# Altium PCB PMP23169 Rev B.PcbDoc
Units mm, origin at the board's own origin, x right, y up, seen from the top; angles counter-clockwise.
Board outline 125.73 x 87.63 mm, 2 copper layers (Top Layer, Bottom Layer), stack 1.575 mm thick; 44 components, 13 nets, 91 pads, 0 vias.
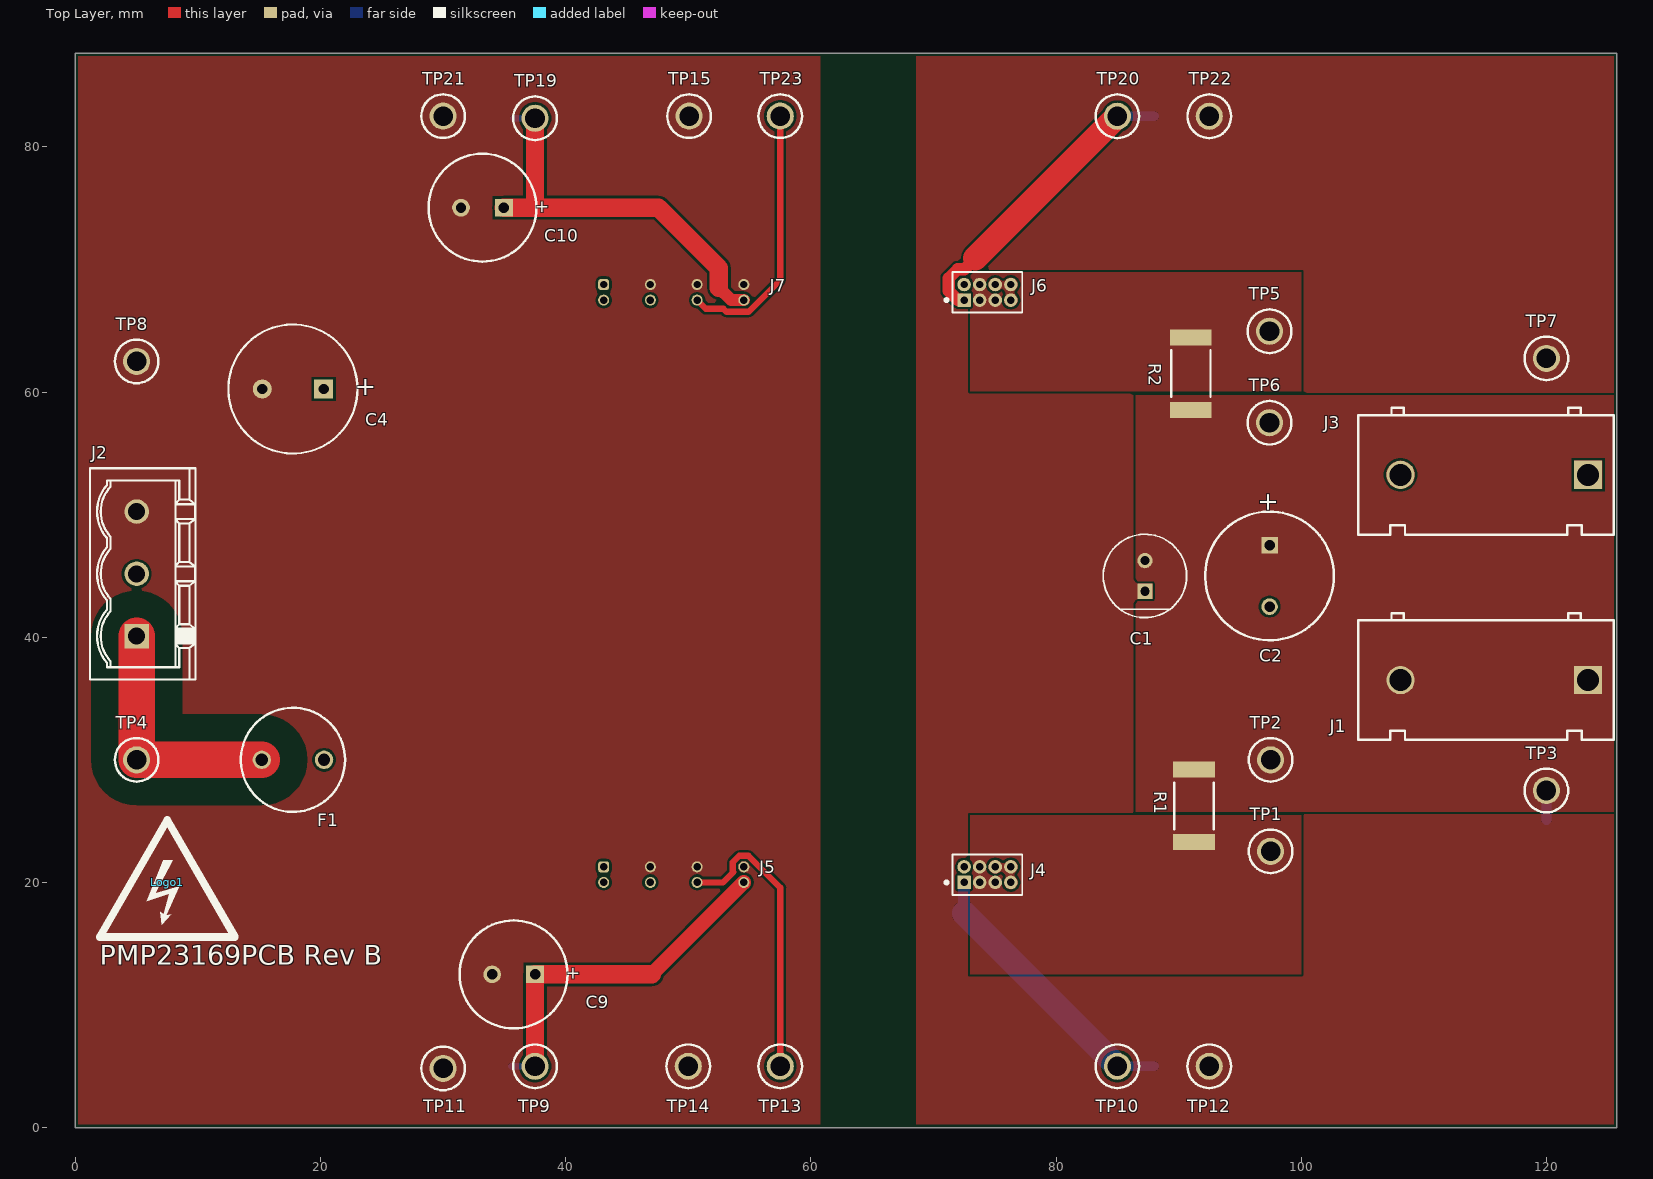
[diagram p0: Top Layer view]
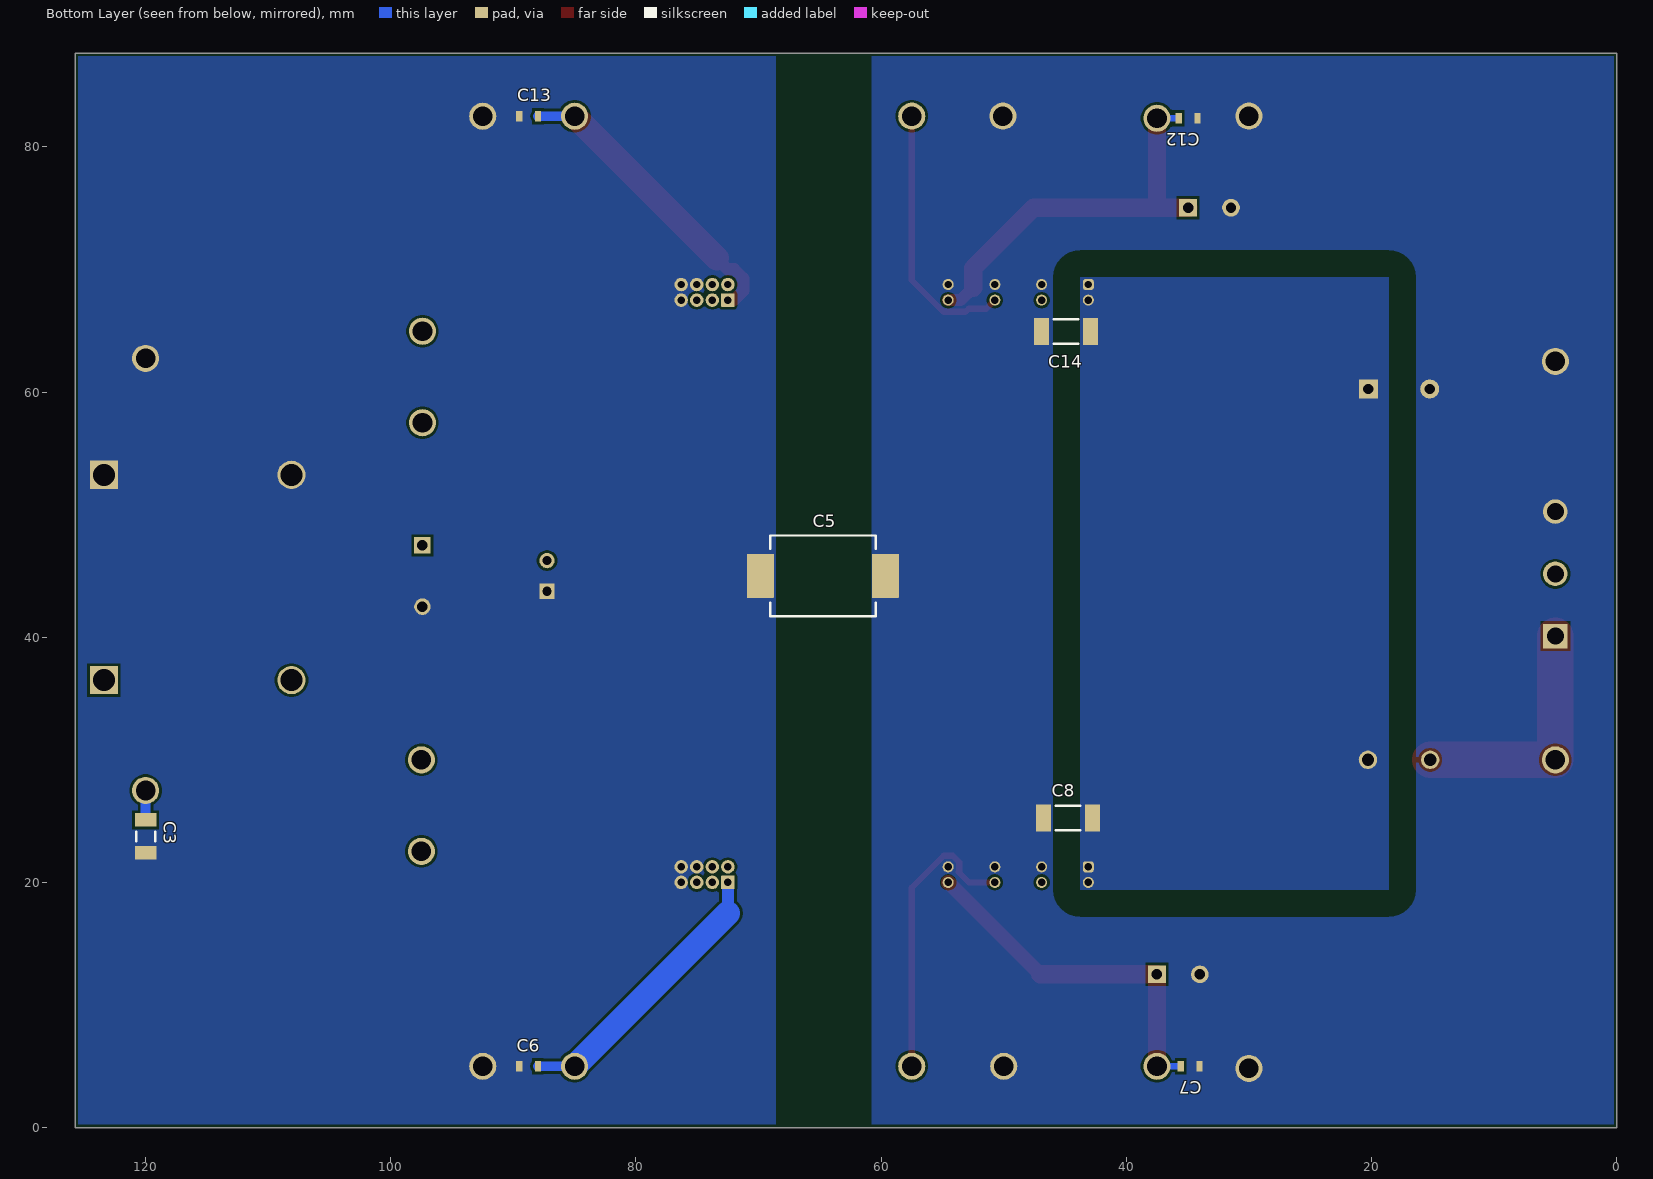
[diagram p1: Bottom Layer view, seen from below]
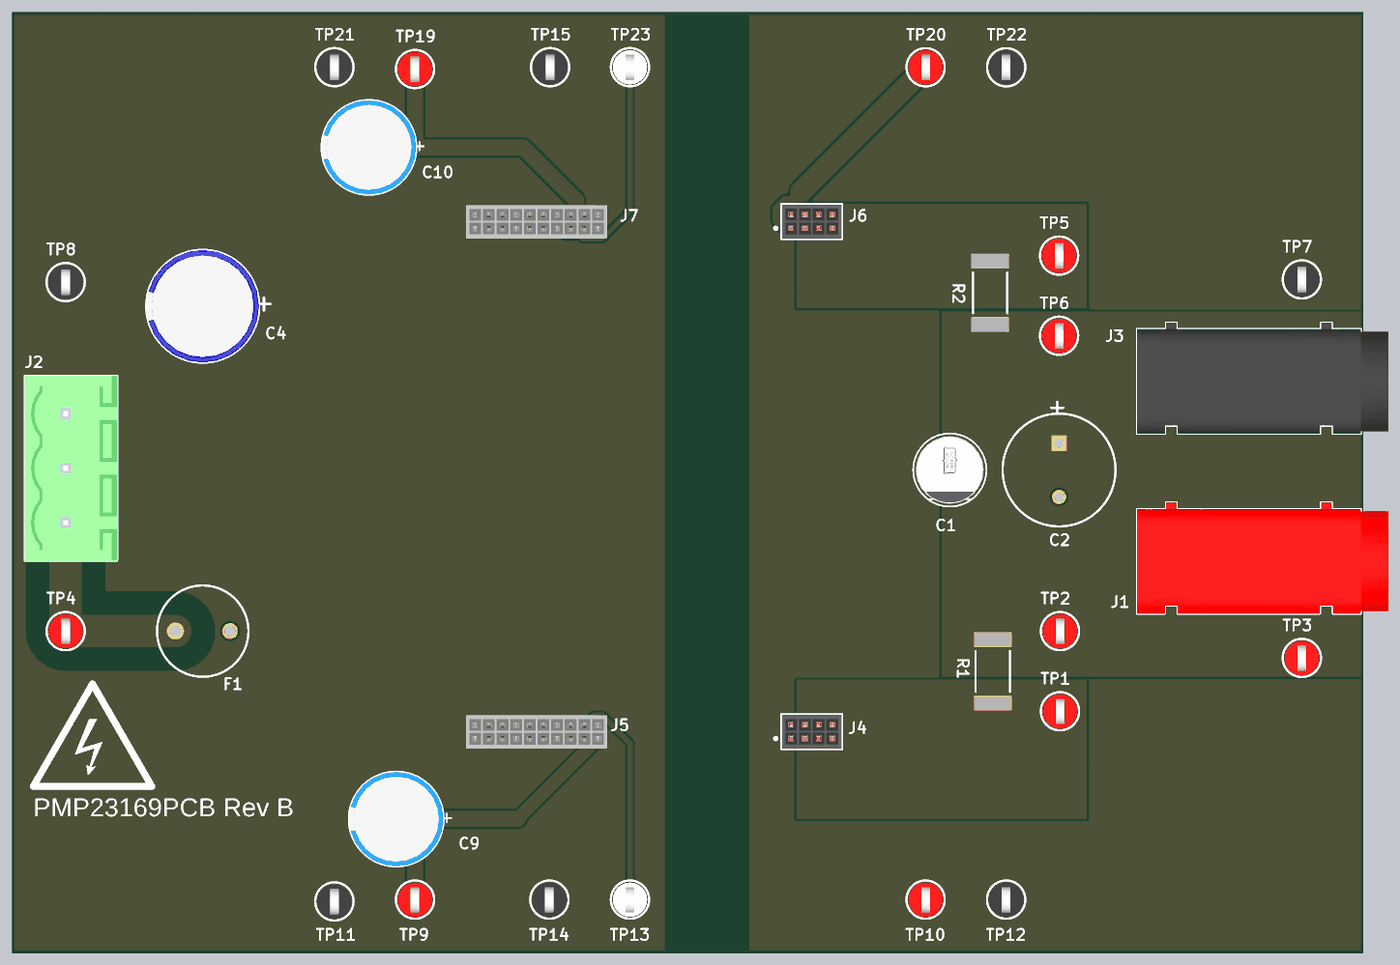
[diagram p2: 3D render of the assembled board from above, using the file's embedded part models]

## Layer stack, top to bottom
Top Solder: solder mask 0.0102, Solder Resist, Dk 3.5
Top Layer: signal copper 0.0356
Dielectric1: core 1.5037, FR-4 High Tg, Dk 4.8
Bottom Layer: signal copper 0.0356
Bottom Solder: solder mask 0.0102, Solder Resist, Dk 3.5

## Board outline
0,0 125.73,0 125.73,87.63 0,87.63

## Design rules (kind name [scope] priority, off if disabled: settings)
AcuteAngle [All] p1: minimum=5.00000000000000E+0000 checktracksonly=FALSE
AssemblyTestPointUsage [All] p1: valid=2
BoardOutlineClearance BoardOutlineClearance_Pri [InNet('P')] p1: gap=0.4 ignorepadtopadclearanceinfootprint=FALSE
BoardOutlineClearance BoardOutlineClearance_MountingHoles [OnCopper and InComponentClass('Mounting Holes')] p2: gap=0.635 ignorepadtopadclearanceinfootprint=FALSE
BoardOutlineClearance BoardOutlineClearance_Poly [OnCopper and InPoly] p3: gap=0.25 ignorepadtopadclearanceinfootprint=FALSE
BoardOutlineClearance [OnCopper and Not InComponentClass('Logo') and not InComponentClass('FiducialMark') and not InRegion(1000,500,4000,800)] p4: gap=0.25 ignorepadtopadclearanceinfootprint=FALSE
Clearance "Pri To Sec Inner Layers" [InNet('S') vs InNet('A')  Or InNet('B')] p1: gap=0.5 ignorepadtopadclearanceinfootprint=TRUE
Clearance "400V Clearance" [(InNetClass('400V') AND (OnTopLayer Or OnBottomLayer)) vs (InNetClass('Primary LV'))] p2: gap=2.2 ignorepadtopadclearanceinfootprint=TRUE
Clearance "Float Bias Clearance" [(InNetClass('BIAS_FLOAT') AND (OnTopLayer Or OnBottomLayer)) vs (InNetClass('Primary LV'))] p3: gap=2.2 ignorepadtopadclearanceinfootprint=TRUE
Clearance Clearance_Keepouts [((IsTrack Or IsArc) And Not InPoly) And IsFree and IsKeepOut vs ((IsTrack Or IsArc) And Not InPoly) And IsFree and IsKeepOut] p4: gap=0 ignorepadtopadclearanceinfootprint=TRUE
Clearance Clearance_Poly [InPolygon] p5: gap=0.203 ignorepadtopadclearanceinfootprint=TRUE except(0: Arc-Hole Track-Hole SMDPad-Hole THPad-Hole Via-Hole Fill-Hole Poly-Hole Region-Hole Text-Hole)
Clearance [All] p6: gap=0.2 ignorepadtopadclearanceinfootprint=TRUE except(0: Arc-Hole Track-Hole SMDPad-Hole THPad-Hole Via-Hole Fill-Hole Poly-Hole Region-Hole Text-Hole)
ComponentClearance ComponentClearance_MountingHoles_FiducialMarks [InComponentClass('Mounting Holes') vs InComponentClass('FiducialMark')] p1: gap=1.27 collisioncheckmode=3 verticalgap=0.254 showdistances=FALSE
ComponentClearance ComponentClearance_Shunt [InComponentClass('Header') vs InComponentClass('Shunt')] p2: gap=0 collisioncheckmode=3 verticalgap=0 showdistances=FALSE
ComponentClearance ComponentClearance_Logo [InComponentClass('Logo')] p3: gap=1.27 collisioncheckmode=3 verticalgap=0.254 showdistances=FALSE
ComponentClearance ComponentClearance_ScrewToNut [(HasFootprint('NY PMS 440 0025 PH')) vs (HasFootprint('Keystone_1902C'))] p4: gap=0.127 collisioncheckmode=3 verticalgap=0.254 showdistances=FALSE
ComponentClearance ComponentClearance_MountingHoles [InComponentClass('Mounting Holes')] p5: gap=6.35 collisioncheckmode=3 verticalgap=2540 showdistances=FALSE
ComponentClearance ComponentClearance_SmallPassives [HasFootprint('0201*') or HasFootprint('0402*') or HasFootprint('0508') or HasFootprint('0603*') or HasFootprint('0612') or HasFootprint('0805*') or HasFootprint('0815*') or HasFootprint('0830*') or HasFootprint('1206*') or HasFootprint('1210*') or HasFootprint('1808*') or HasFootprint('1812*') or HasFootprint('1825*') or HasFootprint('2010*') or HasFootprint('2220*') or HasFootprint('2225*') or HasFootprint('2512*') or HasFootprint('2728*') or HasFootprint('3518*') vs HasFootprint('0201*') or HasFootprint('0402*') or HasFootprint('0508') or HasFootprint('0603*') or HasFootprint('0612') or HasFootprint('0805*') or HasFootprint('0815*') or HasFootprint('0830*') or HasFootprint('1206*') or HasFootprint('1210*') or HasFootprint('1808*') or HasFootprint('1812*') or HasFootprint('1825*') or HasFootprint('2010*') or HasFootprint('2220*') or HasFootprint('2225*') or HasFootprint('2512*') or HasFootprint('2728*') or HasFootprint('3518*')] p6: gap=0.38 collisioncheckmode=3 verticalgap=0.254 showdistances=FALSE
ComponentClearance ComponentClearance_THtoSMT [IsThruComponent vs IsSMTComponent] p7: gap=0.381 collisioncheckmode=3 verticalgap=0.762 showdistances=FALSE
ComponentClearance ComponentClearance_THtoTH [IsThruComponent vs IsThruComponent] p8: gap=0.381 collisioncheckmode=3 verticalgap=0.762 showdistances=FALSE
ComponentClearance [All] p9: gap=0.381 collisioncheckmode=3 verticalgap=0.254 showdistances=FALSE
DiffPairsRouting [All] p1: maxlimit=2.54 minlimit=0.254 mostfreqgap=0.254 toplayer_minwidth=0.381 toplayer_maxwidth=0.381 toplayer_prefwidth=0.381 bottomlayer_minwidth=0.381 bottomlayer_maxwidth=0.381 bottomlayer_prefwidth=0.381 maxuncoupledlength=25.4
FabricationTestPointUsage TestPointUsage [All] p1: valid=2 allowmultiple=FALSE
FabricationTestpoint Testpoint [All] p1: side=3 testpointundercomponent=TRUE minsize=1.016 maxsize=2.54 preferedsize=1.524 minholesize=0 maxholesize=1.016 preferedholesize=0.813 testpointgrid=0.025 allowsidetop=TRUE allowsidebottom=TRUE usegrid=TRUE gridtolerance=0
FanoutControl Fanout_LCC [IsLCC] p1: bgadir=Out bgaviamode=Centered fanoutstyle=Auto fanoutdirection=Alternating viagrid=0.025 // Fanout_LCC (Default Rule)
FanoutControl Fanout_BGA [IsBGA] p2: bgadir=Out bgaviamode=Centered fanoutstyle=Auto fanoutdirection=Alternating viagrid=0.025 // Fanout_BGA (Default Rule)
FanoutControl Fanout_Default [All] p4: bgadir=Out bgaviamode=Centered fanoutstyle=Auto fanoutdirection=Alternating viagrid=0.025 // Fanout_Default (Default Rule)
FanoutControl Fanout_Small [(CompPinCount < 5)] p5: bgadir=Out bgaviamode=Centered fanoutstyle=Auto fanoutdirection=OutThenIn viagrid=0.025 // Fanout_Small (Default Rule)
HoleSize [All] p1: absolutevalues=TRUE maxlimit=6.375 minlimit=0.2 maxpercent=80.000 minpercent=20.000
MinimumAnnularRing MinimumAnnularRing_ThermalPadVias [IsVia and InAnyComponent] p1: minimumring=0.15
MinimumAnnularRing [All] p2: minimumring=0.15
MinimumSolderMaskSliver MinimumSolderMaskSliver_Logo [InComponentClass('Logo') vs InComponentClass('Logo')] p1 off: minsoldermaskwidth=0.018
MinimumSolderMaskSliver [All] p2 off: minsoldermaskwidth=0.025
PlaneConnect [All] p1: planeconnectstyle=Direct reliefexpansion=0.254 reliefentries=4 reliefconductorwidth=0.254 reliefairgap=0.254
PolygonConnect [All] p1: connectstyle=Direct reliefconductorwidth=0.381 reliefentries=4 polygonreliefangle="90 Angle" airgapwidth=0.254
RoutingVias ThermalPadVias [IsVia and InAnyComponent] p1: holewidth=0.2 width=0.5 viastyle="Through Hole" minholewidth=0.2 minwidth=0.5 maxholewidth=0.33 maxwidth=0.6
RoutingVias [All] p2: holewidth=0.406 width=0.864 viastyle="Through Hole" minholewidth=0.2 minwidth=0.65 maxholewidth=1.016 maxwidth=1.651
SilkToBoardRegionClearance [Not ((IsComment or IsDesignator) And (Hide <> 'False')) and not InRegion(1000,500,4000,800)] p1:
SilkToSilkClearance SilkToSilkClearance_Pb-FreeLogo [(HasFootprint('Pb-Free_Overlay_Medium') OR HasFootprint('Pb-Free_Overlay_Small')) vs (HasFootprint('Pb-Free_Overlay_Medium') OR HasFootprint('Pb-Free_Overlay_Small'))] p1: silktosilkclearance=0
SilkToSilkClearance [All] p2: silktosilkclearance=0.025
SilkToSolderMaskClearance SilkToComponentPadClearance [IsPad and InAnycomponent] p1: minsilkscreentomaskgap=0 clearancetoexposedcopper=TRUE
SilkToSolderMaskClearance "Silk to Solder Mask Opening" [All] p2: minsilkscreentomaskgap=0 clearancetoexposedcopper=FALSE
SolderMaskExpansion [All] p1: expansion=0.05 istentingtop=FALSE
Width [All] p1: maxlimit=4 minlimit=0.152 preferedwidth=0.254 checkconnectedcopper=TRUE
15 further rules are at their usual default settings.

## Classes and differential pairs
net class "Primary LV": PGND
net class 400V: NetF1_2 VIN

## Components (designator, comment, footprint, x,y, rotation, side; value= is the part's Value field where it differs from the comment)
C1 "APSG160ELL271MF08J" FP-APSG160ELL271MF08J_RADIAL-MFG 87.25,45 r90 top value=270µF
C2 "EKZE160ELL102MJ20S" Chemi-Con_1000x2000 97.415,45 r270 top value=1000uF
C3 "C3216X5R1V226M160AC" 1206_180L 120,23.75 r270 bottom value=22uF
C4 "EEUEE2W100U" EE_1000x2000 17.75,60.25 r180 top value=10uF
C5 "DK1E3EA152M86RAH01" DK1_86 64.75,45 r180 bottom value=1500pF
C6 "C1608X7R1E105K080AB" 0603S 88.762,5 r180 bottom value=1uF
C7 "C1608X7R1E105K080AB" 0603S 34.795,5 r0 bottom value=1uF
C8 "C1808W104KBRACTU" 1808_215_L 44.75,25.25 r0 bottom value=0.1uF
C9 "UBT1E101MPD1TD" BT_800x1150 35.75,12.5 r180 top value=100uF
C10 "UBT1E101MPD1TD" BT_800x1150 33.21,75.04 r180 top value=100uF
C12 "C1608X7R1E105K080AB" 0603S 34.96,82.336 r0 bottom value=1uF
C13 "C1608X7R1E105K080AB" 0603S 88.75,82.5 r180 bottom value=1uF
C14 "C1808W104KBRACTU" 1808_215_L 44.914,64.94 r0 bottom value=0.1uF
F1 "37205000001" FUSE_372 17.75,30 r180 top
J1 "571-0500" 571-0500 115.75,36.5 r180 top
J2 "1755749" CONN_1755749 5,45.17 r90 top
J3 "571-0100" 571-0100 115.75,53.25 r180 top
J4 "LPPB042CFFN-RC" FP-LPPB042CFFN-RC_HDR8-MFG 74.405,20.635 r0 top
J5 "LPPB102CFFN-RC" Sullins_LPPB102CFFN 48.815,20.635 r0 top
J6 "LPPB042CFFN-RC" FP-LPPB042CFFN-RC_HDR8-MFG 74.405,68.135 r0 top
J7 "LPPB102CFFN-RC" Sullins_LPPB102CFFN 48.815,68.135 r0 top
Logo1 "DANGER HIGH VOLTAGE" IEC_HighVoltage_Medium 7.5,20 r0 top (schematic designator LOGO1)
R1 "WSL2512R0100FEA" 2512 91.25,26.25 r90 top value=0.01
R2 "WSL2512R0100FEA" 2512 91,61.5 r270 top value=0.01
TP1 "5010" Keystone5010 97.5,22.536 r0 top
TP2 "5010" Keystone5010 97.5,30 r0 top
TP3 "5010" Keystone5010 120,27.5 r0 top
TP4 "5010" Keystone5010 5,30 r0 top
TP5 "5010" Keystone5010 97.415,64.963 r0 top
TP6 "5010" Keystone5010 97.415,57.5 r0 top
TP7 "5011" Keystone5011 120,62.75 r0 top
TP8 "5011" Keystone5011 5,62.5 r0 top
TP9 "5010" Keystone5010 37.5,5 r0 top
TP10 "5010" Keystone5010 85,5 r0 top
TP11 "5011" Keystone5011 30,4.828 r0 top
TP12 "5011" Keystone5011 92.494,5 r0 top
TP13 "5012" Keystone5012 57.5,5 r0 top
TP14 "5011" Keystone5011 50,5 r0 top
TP15 "5011" Keystone5011 50.067,82.509 r0 top
TP19 "5010" Keystone5010 37.5,82.336 r0 top
TP20 "5010" Keystone5010 85,82.5 r0 top
TP21 "5011" Keystone5011 30,82.509 r0 top
TP22 "5011" Keystone5011 92.5,82.5 r0 top
TP23 "5012" Keystone5012 57.5,82.509 r0 top

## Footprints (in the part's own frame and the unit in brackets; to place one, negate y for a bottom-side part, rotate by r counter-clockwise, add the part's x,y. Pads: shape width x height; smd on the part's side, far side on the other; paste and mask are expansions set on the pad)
571-0100 [mm] "Deltron Emcon recommended land pattern 2003-10-13"
  rect 2.3x2.3 hole 1.8: 1(-7.65,0)
  round 2.3 hole 1.8: 2(7.65,0)
  silkscreen extent -9.74,-5.47 11.09,4.88, body extent -12.28,-5.48 11.09,4.88, height 12.41
571-0500 [mm] "Deltron Emcon recommended land pattern 2003-10-13"
  rect 2.3x2.3 hole 1.8: 1(-7.65,0)
  round 2.3 hole 1.8: 2(7.65,0)
  silkscreen extent -9.74,-5.47 11.09,4.88, body extent -12.28,-5.48 11.09,4.88, height 12.41
0603S [mil]
  rect 20x35 smd: 1(-30,0) 2(30,0)
  body extent -34,-19 34,19, height 39
1206_180L [mm] "1206_180"
  rect 1.1x1.75 smd: 1(-1.35,0) 2(1.35,0)
  silkscreen extent -0.4,-0.77 0.4,0.77, body extent -1.75,-0.95 1.75,0.95, height 1.8
1808_215_L [mm] "Chip Capacitor, Body 4.6x2.0mm, IPC High Density"
  rect 1.2x2.2 smd: 1(-2,0) 2(2,0)
  silkscreen extent -1,-1 1,1, body extent -2.47,-1.2 2.47,1.2, height 2.15
2512 [mm] "Chip Resistor, Body 6.3x3.2mm, IPC Medium Density"
  rect 1.3x3.4 smd: 1(-2.95,0) 2(2.95,0)
  silkscreen extent -1.9,-1.6 1.9,1.6, body extent -3.22,-1.67 3.22,1.67, height 0.71
BT_800x1150 [mm] "Nichicon"
  rect 1.45x1.45 hole 0.85: 1(-1.75,0)
  round 1.45 hole 0.85: 2(1.75,0)
  silkscreen extent -4.4,-4.4 4.4,4.4, body extent -4.37,-4.39 4.39,4.39, height 12.52
Chemi-Con_1000x2000 [mm] "TH, 2-Leads, Body 10x20mm, Pin Spacing 5mm"
  rect 1.35x1.35 hole 0.85: 1(-2.5,0)
  round 1.35 hole 0.85: 2(2.5,0)
  silkscreen extent -5.25,-5.25 5.25,5.25, body extent -5.25,-5.25 5.25,5.25, height 21.5
CONN_1755749 [mm] "Phoenix Contact"
  rect 2x2 hole 1.4: 1(-5.08,0)
  round 2 hole 1.4: 2(0,0) 3(5.08,0)
  silkscreen extent -8.62,-4.8 8.62,3.8, body extent -8.62,-4.8 8.62,3.8, height 12.02
DK1_86 [mm] "SMD, 2-Leads, Body 8x6mm"
  rrect5% 2.2x3.6 smd: 1(-5.1,0) 2(5.1,0)
  silkscreen extent -4.3,-3.3 4.3,3.3, body extent -5.95,-3.25 5.95,3.25, height 2.5
EE_1000x2000 [mm] "PANASONIC"
  rect 1.55x1.55 hole 0.85: 1(-2.5,0)
  round 1.55 hole 0.85: 2(2.5,0)
  silkscreen extent -5.26,-5.26 5.26,5.26, body extent -5.21,-5.24 5.24,5.24, height 22.01
FP-APSG160ELL271MF08J_RADIAL-MFG [mm]
  rrect8% 1.25x1.25 hole 0.75 paste-1000 mask+0: 1(-1.25,0)
  round 1.25 hole 0.75 paste-1000 mask+0: 2(1.25,0)
  silkscreen extent -3.4,-3.4 3.4,3.4, body extent -3.5,-3.5 3.5,3.5, height 0.25
FP-LPPB042CFFN-RC_HDR8-MFG [mm]
  rrect9% 1.1x1.1 hole 0.6 paste-1000 mask+0: 1(-1.905,-0.635)
  round 1.1 hole 0.6 paste-1000 mask+0: 2(-1.905,0.635) 3(-0.635,-0.635) 4(-0.635,0.635) 5(0.635,-0.635) 6(0.635,0.635) 7(1.905,-0.635) 8(1.905,0.635)
  silkscreen extent -3.46,-1.65 2.84,1.65, body extent -2.94,-1.75 2.94,1.75, height 0.25
FUSE_372 [mm] "LITTELFUSE"
  round 1.5 hole 1: 1(-2.54,0) 2(2.54,0)
  silkscreen extent -4.25,-4.25 4.25,4.25, body extent -4.25,-4.25 4.25,4.25, height 8
IEC_HighVoltage_Medium [mm]
  silkscreen extent -5.51,-4.46 5.51,5.09
Keystone5010 [mil] "Keystone Multipurpose loops"
  round 87 hole 63: 1(0,0)
  silkscreen extent -70,-70 70,70, body extent -63,-63 63,62, height 319
Keystone5011 [mil] "Keystone Multipurpose loops"
  round 87 hole 63: 1(0,0)
  silkscreen extent -70,-70 70,70, body extent -63,-63 63,62, height 319
Keystone5012 [mil] "Keystone Multipurpose loops"
  round 87 hole 63: 1(0,0)
  silkscreen extent -70,-70 70,70, body extent -63,-63 63,62, height 319
Sullins_LPPB102CFFN [mm] "Receptacle, 1.27 mm, TH"
  rrect50% 0.9x0.9 hole 0.6: 1(-5.715,0.635)
  round 0.9 hole 0.6 mask+0.102: 2(-5.715,-0.635) 8(-1.905,-0.635) 14(1.905,-0.635) 20(5.715,-0.635)
  round 0.9 hole 0.6: 7(-1.905,0.635) 13(1.905,0.635) 19(5.715,0.635)
  body extent -6.55,-1.56 6.55,1.54, height 4.5

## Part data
C1: library part CMP-0091874-1, "270µF 16V Aluminum - Polymer Capacitors Radial, Can 10mOhm 20000 Hrs @ 105°C", Digikey Part Number=565-4812-ND, Leakage Current=864uA, Manufacturer="Nippon Chemi-Con", Mouser Part Number=661-APSG160E271MF08J, Operating Temperature Range="-55°C to +105°C", Tolerance_%=20%, ValueDisplayed=270uF
C2: library part CMP-0010386-1, "CAP, AL, 1000 uF, 16 V, +/- 20%, TH", Cap_Case=10x20, Manufacturer=Chemi-Con, Supplier Part Number 1=565-1664-ND, Tolerance_%=20%, Value1=Unknown, Value2=16V, ValueDisplayed=1000uF
C3: library part CMP-0008667-2, "CAP, CERM, 22 uF, 35 V, +/- 20%, X5R, 1206", Cap_Case=1206_180, Manufacturer=TDK, Supplier Part Number 1=445-8045-1-ND, TempCo=X5R, Tolerance_%=20%, Value1="0.002398 ohm", Value2=35V, ValueDisplayed=22uF
C4: library part CMP-0010028-3, "CAP, AL, 10 uF, 450 V, +/- 20%, TH", Cap_Case=10x20mm, Manufacturer=Panasonic, Supplier Part Number 1=P13671-ND, Tolerance_%=20%, Value1=Unknown, Value2=450V, ValueDisplayed=10uF
C5: library part CMP-0077998-1, "CAP, CERM, 1500 pF, X1 440 VAC/Y1 250 VAC, +/- 20%, E, 8x6mm", Cap_Case=8x6mm, Manufacturer=MuRata, Supplier Part Number 1=490-16264-1-ND, TempCo=E, Tolerance_%=20%, ValueDisplayed=1500pF
C6 C7 C12 C13: library part CMP-0007040-4, "CAP, CERM, 1 µF, 25 V, +/- 10%, X7R, 0603", Cap_Case=0603, Manufacturer=TDK, Supplier Part Number 1=445-5956-1-ND, TempCo=X7R, Tolerance_%=10%, Value1=Unknown, Value2=25V, ValueDisplayed=1uF
C8 C14: library part CMP-0009318-2, "CAP, CERM, 0.1 uF, 630 V, +/- 10%, X7R, 1808", Cap_Case=1808, Manufacturer=Kemet, Supplier Part Number 1=399-6515-1-ND, TempCo=X7R, Tolerance_%=10%, Value1=Unknown, Value2=630V, ValueDisplayed=0.1uF
C9 C10: library part CMP-0010526-1, "CAP, AL, 100 uF, 25 V, +/- 20%, 0.13 ohm, TH", Cap_Case=8x11.5, Manufacturer=Nichicon, Supplier Part Number 1=493-4496-1-ND, Tolerance_%=20%, Value1="0.13 ohm", Value2=25V, ValueDisplayed=100uF
F1: library part CMP-0003549-2, "Fuse, 0.5 A, 250VAC/VDC, TH", Irating_A=500mA, Manufacturer=Littelfuse, Supplier Part Number 1=WK4241CT-ND
J1: library part CMP-0055393-3, "Standard Banana Jack, insulated, 10A, red", Manufacturer="DEM Manufacturing", Supplier Part Number 1=30M0087
J2: library part CMP-0055478-1, "Terminal Block, 3x1, 5.08 mm, TH", Manufacturer="Phoenix Contact", Supplier Part Number 1=277-1151-ND
J3: library part CMP-0055389-3, "Standard Banana Jack, insulated, 10A, black", Manufacturer="DEM Manufacturing", Supplier Part Number 1=45M6896
J4 J6: library part CMP-0093817-1, Current_A=1A, Digikey Part Number=S9009E-04-ND, Manufacturer="Sullins Connector Solutions", Operating Temperature Range="-40°C to +125°C"
J5 J7: library part CMP-BK1, "Receptacle, 1.27mm, 10x2, Gold, TH", Color=Black, Current_A=1A, Manufacturer="Sullins Connector Solutions"
Logo1: library part CMP-0074835-1, "IEC 61010-1 High Voltage Warning"
R1 R2: library part CMP-0015850-2, "RES, 0.01, 1%, 1 W, 2512", Manufacturer=Vishay-Dale, Power_W=1W, Supplier Part Number 1=WSLG-.01CT-ND, TempCo="75 ppm/C", Tolerance_%=1%, Value_Code=R010, ValueDisplayed=0.01
TP1 TP2 TP3 TP4 TP5 TP6 TP9 TP10 TP19 TP20: library part CMP-0055147-1, "Test Point, Multipurpose, Red, TH", Color=Red, Manufacturer=Keystone, Supplier Part Number 1=36-5010-ND
TP7 TP8 TP11 TP12 TP14 TP15 TP21 TP22: library part CMP-0055148-1, "Test Point, Multipurpose, Black, TH", Color=Black, Manufacturer=Keystone, Supplier Part Number 1=36-5011-ND
TP13 TP23: library part CMP-0055149-1, "Test Point, Multipurpose, White, TH", Color=White, Manufacturer=Keystone, Supplier Part Number 1=36-5012-ND

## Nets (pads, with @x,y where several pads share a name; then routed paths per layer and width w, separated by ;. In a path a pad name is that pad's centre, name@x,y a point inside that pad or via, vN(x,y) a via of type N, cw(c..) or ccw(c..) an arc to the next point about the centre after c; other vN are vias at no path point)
12VSA_1: C6.2 J4.1 TP10.1 | length 23.2
  Bottom Layer w0.8: TP10.1 C6.2
  Bottom Layer w1: 72.5,17.5 J4.1
  Bottom Layer w2: 72.5,17.5 TP10.1
12VSA_2: C13.2 J6.1 TP20.1 | length 24.8
  Top Layer w1: J6.1 72.283,67.5 72.263,67.52 71.982,67.52 71.25,68.252 71.25,69.288 71.982,70.02 72.52,70.02 73.42,70.92
  Top Layer w2: 73.42,70.92 TP20.1
  Bottom Layer w0.8: TP20.1 C13.2
12VSB_1: J4.3 J4.4 J4.5 R1.1 TP1.1
12VSB_2: J6.3 J6.4 J6.5 R2.1 TP5.1
12VSB_OUT: C1.2 C2.1 C3.1 J1.1 J1.2 R1.2 R2.2 TP2.1 TP3.1 TP6.1 | length 2.4
  Bottom Layer w0.8: C3.1 TP3.1
DIS_1: J5.14 TP13.1 | length 23.9
  Top Layer w0.5: J5.14 52.833,20 53.68,20.847 53.63,20.897 53.63,21.643 54.157,22.17 54.903,22.17 57.51,19.563 57.5,19.553 TP13.1
DIS_2: J7.14 TP23.1 | length 21.6
  Top Layer w0.5: J7.14 51.429,66.791 52.866,66.791 53.106,66.55 54.924,66.55 57.5,69.126 TP23.1
GND: C1.1 C2.2 C3.2 C5.1 C6.1 C13.1 J3.1 J3.2 J4.6 J4.7 J4.8 J6.6 J6.7 J6.8 TP7.1 TP12.1 TP22.1
NetF1_2: F1.2 J2.1 TP4.1 | length 20.3
  Top Layer w3: J2.1 TP4.1 F1.2
P12V_1: C7.2 C9.1 J5.20 TP9.1 | length 29.6
  Top Layer w1.2: 47.03,12.5 J5.20
  Top Layer w1.5: TP9.1 C9.1 47.03,12.5
  Bottom Layer w0.5: C7.2 TP9.1
P12V_2: C10.1 C12.2 J7.20 TP19.1 | length 32.8
  Top Layer w1: 52.5,68.5 53.5,67.5 J7.20
  Top Layer w1.5: C10.1 37.61,75.04 ; TP19.1 37.5,75.15 37.61,75.04 ; 52.5,68.5 52.5,70.103 47.563,75.04 37.61,75.04
  Bottom Layer w0.5: C12.2 TP19.1
PGND: C4.2 C5.2 C7.1 C8.2 C9.2 C10.2 C12.1 C14.2 J2.3 J5.7 J5.13 J5.19 J7.7 J7.13 J7.19 TP8.1 TP11.1 TP14.1 TP15.1 TP21.1
VIN: C4.1 C8.1 C14.1 F1.1 J5.1 J5.2 J7.1 J7.2
pads on no net: J2.2 J4.2 J5.8 J6.2 J7.8

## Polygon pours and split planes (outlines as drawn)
GND on Bottom Layer "BOTTOM_LAYER_GND_P007" (solid, remove dead copper, pour order 7): 68.603,87.63 68.603,0 125.73,0 125.73,87.63
PGND on Bottom Layer "BOTTOM_LAYER_PGND_P001" (solid, remove dead copper, pour order 1): 0,87.63 0,0 60.75,0 60.75,87.63
VIN on Bottom Layer "BOTTOM_LAYER_VIN_P000" (solid, remove dead copper, pour order 0): 18.603,69.37 18.603,19.403 43.75,19.403 43.75,69.37
GND on Top Layer "TOP_LAYER_GND_P006" (solid, remove dead copper, pour order 6): 68.603,87.63 68.603,0 125.73,0 125.73,87.63
12VSB_1 on Top Layer "TOP_LAYER_12VSB_1_P005" (solid, remove dead copper, pour order 5): 73.004,25.482 73.004,12.5 99.996,12.5 99.996,25.482
12VSB_2 on Top Layer "TOP_LAYER_12VSB_2_P004" (solid, remove dead copper, pour order 4): 73.008,69.785 73.008,60.053 100,60.053 100,69.785
12VSB_OUT on Top Layer "TOP_LAYER_12VSB_OUT_P003" (solid, remove dead copper, pour order 3): 86.5,59.75 86.5,25.75 125.73,25.75 125.73,59.75
PGND on Top Layer "TOP_LAYER_PGND_P002" (solid, remove dead copper, pour order 2): 0,87.63 0,0 60.75,0 60.75,87.63

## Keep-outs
Keep-Out Layer:
  text ".Layer_Name" at 14.656,-21.806 h1.52

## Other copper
Top Layer:
  text ".Layer_Name" at 14.656,-21.806 h1.52
Bottom Layer:
  text ".Layer_Name" at 14.656,-21.806 h1.52

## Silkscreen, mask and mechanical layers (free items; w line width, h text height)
Top Overlay:
  text "PMP23169PCB Rev B" at 1.988,12.75 h2.75
  text ".Layer_Name" at 14.656,-21.806 h1.52
Bottom Overlay:
  text ".Layer_Name" at 14.656,-21.806 h1.52
Top Paste:
  text ".Layer_Name" at 14.656,-21.806 h1.52
Bottom Paste:
  text ".Layer_Name" at 14.656,-21.806 h1.52
Top Solder:
  text ".Layer_Name" at 14.656,-21.806 h1.52
  text ".Layer_Name" at 14.656,-21.806 h1.52
Bottom Solder:
  text ".Layer_Name" at 14.656,-21.806 h1.52
Drill Guide:
  text ".Layer_Name" at 14.656,-21.806 h1.52
M1 Board Outline:
  the board outline again, w0.254
  text ".Layer_Name" at 14.656,-21.806 h1.52
M2 Board Dimensions:
  rectangle: 0,-6.985 3.175,-3.81
  rectangle: 3.175,-10.16 12.7,-6.985
  lines w0.178: 0,-6.985 25.4,-6.985 ; 3.175,-10.16 3.175,-3.81 ; 6.35,-10.16 6.35,-3.81 ; 12.7,-10.16 12.7,-3.81 ; 19.05,-10.16 19.05,-3.81 ; 0,-10.16 25.4,-10.16 25.4,-3.81 0,-3.81 0,-10.16
  text ".Layer_Name" at 14.656,-21.806 h1.52
M3 3D STEP Top:
  text ".Layer_Name" at 14.656,-21.806 h1.52
M4 3D STEP Bottom:
  text ".Layer_Name" at 14.656,-21.806 h1.52
M5 Assembly Top:
  lines w0.254: -7.417,-23.626 160.223,-23.626 ; -7.417,-18.462 160.274,-18.462 ; -7.417,-13.297 -7.417,-28.791 94.31,-28.791 160.274,-28.791 160.274,-13.297 -7.404,-13.297 -7.404,-28.791 32.614,-28.791 ; 55.194,-28.791 55.194,-13.297 ; 87.376,-18.462 87.376,-13.297 ; 108.712,-18.462 108.712,-13.297 ; 124.511,-28.956 124.511,-23.804
  text "COMPONENTS MARKED 'DNP' SHOULD NOT BE POPULATED." at 29.299,-8.09 h1.52
  text "ASSEMBLY VARIANT:" at 29.286,-11.024 h1.52
  text ".VariantName" at 55.601,-11.024 h1.52
  text "PCB VIEWED FROM TOP SIDE" at -5.804,-16.654 h1.52
  text "BOARD #:" at 57.099,-16.654 h1.52
  text ".PRJ_Number" at 70.955,-16.654 h1.52
  text "REV:" at 92.405,-16.654 h1.52
  text ".PCB_Rev" at 99.809,-16.654 h1.52
  text "SVN REV:" at 113.69,-16.654 h1.52
  text ".VersionControl_RevNumber" at 126.543,-16.654 h1.52
  text "TID #:" at 57.099,-21.819 h1.52
  text ".TID" at 70.955,-21.819 h1.52
  text "PLOT NAME =" at -5.804,-27.034 h1.52
  text ".plot_File_Name" at 14.656,-27.034 h1.52
  text "GENERATED    :" at 57.15,-27.034 h1.52
  text ".Print_Date" at 79.235,-27.034 h1.52
  text ".Print_Time" at 97.752,-27.034 h1.52
  text "TEXAS INSTRUMENTS" at 129.87,-27.034 h1.52
M6 Assembly Bottom:
  lines w0.254: -7.429,-18.474 160.261,-18.474 ; -7.379,-23.639 160.261,-23.639 ; 28.334,-28.969 28.334,-23.817 ; 44.133,-18.474 44.133,-13.31 ; 65.468,-18.474 65.468,-13.31 ; 97.65,-28.804 97.65,-13.31 ; 120.231,-28.804 160.249,-28.804 160.249,-13.31 -7.429,-13.31 -7.429,-28.804 58.534,-28.804 160.261,-28.804 160.261,-13.31
  text "COMPONENTS MARKED 'DNP' SHOULD NOT BE POPULATED." at 154.991,-8.077 h1.52
  text ".VariantName" at 128.473,-11.024 h1.52
  text "ASSEMBLY VARIANT:" at 154.864,-11.024 h1.52
  text ".VersionControl_RevNumber" at 26.302,-16.667 h1.52
  text "SVN REV:" at 39.154,-16.667 h1.52
  text ".PCB_Rev" at 53.035,-16.667 h1.52
  text "REV:" at 60.439,-16.667 h1.52
  text ".PRJ_Number" at 81.89,-16.667 h1.52
  text "BOARD #:" at 95.745,-16.667 h1.52
  text "PCB VIEWED FROM BOTTOM SIDE" at 158.648,-16.667 h1.52
  text ".TID" at 81.89,-21.831 h1.52
  text "TID #:" at 95.745,-21.831 h1.52
  text "TEXAS INSTRUMENTS" at 22.974,-27.047 h1.52
  text ".Print_Time" at 55.093,-27.047 h1.52
  text ".Print_Date" at 73.609,-27.047 h1.52
  text "GENERATED    :" at 95.694,-27.047 h1.52
  text ".plot_File_Name" at 138.189,-27.047 h1.52
  text "PLOT NAME =" at 158.648,-27.047 h1.52
M9 Title Sheet:
  drawing of 57 lines, arcs and shapes, not listed
  text "1" at 18.792,204.127 h1.78
  text "2" at 82.182,204.127 h1.78
  text "3" at 145.411,204.127 h1.78
  text "4" at 209.08,204.127 h1.78
  text "5" at 272.555,204.127 h1.78
  text "6" at 336.182,204.127 h1.78
  text "A" at -10.579,175.095 h1.78
  text "A" at 365.341,175.095 h1.78
  text "B" at -10.579,114.643 h1.78
  text "B" at 365.341,114.643 h1.78
  text "C" at -10.579,54.318 h1.78
  text "C" at 365.341,54.318 h1.78
  text "PROJECT TITLE:" at 288.125,7.048 h1.14
  text ".PRJ_Title" at 289.395,3.662 h1.78
  text "DESIGNED FOR:" at 288.125,-0.597 h1.14
  text ".PRJ_Customer" at 289.395,-4.153 h1.78
  text "D" at -10.579,-5.88 h1.78
  text "D" at 365.341,-5.88 h1.78
  text "FILE NAME:" at 288.125,-8.217 h1.14
  text ".PCB_File_Name_No_Path" at 289.395,-11.265 h1.78
  text "Texas Instruments (TI) and/or its licensors do not warrant the accuracy or completeness of this specification" at 161.9,-15.376 h1.14
  text "ENGINEER:" at 288.125,-15.583 h1.14
  text "LAYOUT BY:" at 326.352,-15.583 h1.14
  text "or any information contained therein. TI and/or its licensors do not warrant that this design will meet" at 160.757,-18.237 h1.14
  text ".PRJ_Engineer" at 289.395,-19.52 h1.78
  text ".PCB_Layout" at 327.635,-19.52 h1.78
  text "the specifications, will be suitable for your application or fit for any particular purpose, or will operate in" at 160.757,-21.099 h1.14
  text ".Layer_Name" at 14.656,-21.806 h1.52
  text "ALTIUM DESIGNER VERSION:" at 326.352,-23.457 h1.14
  text "an implementation. TI and/or its licensors do not warrant that the design is production worthy. You should" at 160.757,-23.961 h1.14
  text "completely validate and test your design implementation to confirm the system functionality for your application." at 161.9,-26.822 h1.14
  text ".print_Scale" at 289.395,-26.843 h1.78
  text ".Application_BuildNumber" at 327.635,-26.843 h1.78
  text "1" at 18.792,-32.093 h1.78
  text "2" at 82.182,-32.093 h1.78
  text "3" at 145.411,-32.093 h1.78
  text "4" at 209.08,-32.093 h1.78
  text "5" at 272.555,-32.093 h1.78
  text "6" at 336.182,-32.093 h1.78
M10 Fab Notes:
  drawing of 189 lines, arcs and shapes, not listed
  text "DESIGN INFORMATION" at 314.503,161.447 h1.52
  text "MIN. TRACK WIDTH:" at 298.131,158.091 h1.52
  text "8" at 325.976,158.091 h1.52
  text "MIL" at 329.907,158.091 h1.52
  text "7.874" at 321.75,155 h1.52
  text "MIN. CLEARANCE:" at 298.131,154.938 h1.52
  text "MIL" at 329.907,154.938 h1.52
  text "MIN. VIA PAD SIZE:" at 298.131,151.785 h1.52
  text "24" at 325.214,151.785 h1.52
  text "MIL" at 329.907,151.785 h1.52
  text "0.05mm (2MIL)" at 315.784,148.486 h1.52
  text "MINIMUM ANNULAR RING" at 289.769,148.277 h1.52
  text "EXTERNAL" at 333.768,148.277 h1.52
  text "PER" at 294.849,145.48 h1.52
  text "IPC-D-275 CLASS 2 LEVEL C" at 300.437,145.48 h1.52
  text "MIL, HOLES" at 338.238,142.928 h1.52
  text "+/-" at 328.27,142.709 h1.52
  text "+/-" at 349.961,142.709 h1.52
  text "REGISTRATION TOLERANCES:" at 289.769,142.682 h1.52
  text "METAL" at 320.243,142.682 h1.52
  text "5" at 334.879,142.683 h1.52
  text "3" at 356.037,142.683 h1.52
  text "MIL" at 358.99,142.682 h1.52
  text "HOLE SIZE TOLERANCE (UNLESS OTHERWISE SPECIFIED):" at 289.769,140.185 h1.52
  text "+/-" at 349.961,140.112 h1.52
  text "3" at 356.037,140.085 h1.52
  text "MIL" at 358.99,140.085 h1.52
  text "MATERIAL:" at 287.87,136.589 h1.52
  text "FR-4 High Tg" at 312.926,133.324 h1.52
  text "X" at 309.257,133.122 h1.52
  text "FR-408" at 298.563,133.007 h1.52
  text "OTHER" at 336.358,133.007 h1.52
  text "62 MIL (1.6mm) +/-10%" at 306.694,129.374 h1.52
  text "X" at 303.643,129.312 h1.52
  text "THICKNESS:" at 289.769,129.165 h1.52
  text "OTHER" at 339.33,129.165 h1.52
  text "TOLERANCE:" at 289.769,125.652 h1.52
  text "X" at 311.314,125.652 h1.52
  text "ANSI IPC-6012 TYPE 3 CLASS 2" at 315.836,125.652 h1.52
  text "OTHER +/-" at 315.835,121.989 h1.52
  text "BOW & TWIST:" at 289.769,118.302 h1.52
  text "X" at 311.314,118.302 h1.52
  text "ANSI IPC-6012 TYPE 3 CLASS 2" at 315.836,118.302 h1.52
  text "OTHER +/-" at 315.835,114.576 h1.52
  text "DRILLING:" at 287.87,111.258 h1.52
  text "NC_DRILL FILES" at 332.599,108.586 h1.52
  text "REFERENCE:" at 289.769,108.486 h1.52
  text "X" at 306.463,108.484 h1.52
  text "AS SHOWN" at 310.984,108.486 h1.52
  text "X" at 329.348,108.486 h1.52
  text "OTHER" at 340.168,104.873 h1.52
  text "PTH COPPER THICKNESS:" at 289.761,104.783 h1.52
  text "X" at 318.697,104.783 h1.52
  text "20-30 um" at 321.948,104.783 h1.52
  text "BOARD FINISH:" at 287.87,101.034 h1.52
  text "SILKSCREEN:" at 291.812,98.237 h1.52
  text "X" at 316.14,98.237 h1.52
  text "TOP" at 319.112,98.237 h1.52
  text "X" at 329.094,98.237 h1.52
  text "BOTTOM" at 332.091,98.237 h1.52
  text "SILKSCREEN COLOR:" at 291.812,94.295 h1.52
  text "X" at 316.115,94.295 h1.52
  text "WHITE" at 319.112,94.295 h1.52
  text "OTHER" at 332.091,94.295 h1.52
  text "X" at 319.442,90.652 h1.52
  text "GREEN" at 322.439,90.652 h1.52
  text "OTHER" at 338.136,90.652 h1.52
  text "SOLDER RESIST COLOR:" at 291.812,90.477 h1.52
  text "X" at 319.442,86.734 h1.52
  text "MATTE" at 322.439,86.734 h1.52
  text "SEMI-GLOSS" at 338.125,86.717 h1.52
  text "IMMERSION GOLD (ENIG)" at 314.819,82.345 h1.52
  text "ENEPIG" at 348.793,82.162 h1.52
  text "SURFACE FINISH:" at 287.87,82.136 h1.52
  text "X" at 310.298,82.136 h1.52
  text "IMM. TIN/SILVER OR EQUIV" at 296.24,78.649 h1.52
  text "OTHER" at 332.599,78.549 h1.52
  text "ARRAY/PANEL:" at 287.87,74.602 h1.52
  text "CUT AND TRIM PER M1 BOARD OUTLINE" at 314.819,74.393 h1.52
  text "N.C. ROUTE" at 314.819,70.94 h1.52
  text "X" at 332.295,70.94 h1.52
  text "V. SCORE" at 336.816,70.94 h1.52
  text "CERTIFICATION:" at 287.87,67.66 h1.52
  text "MATERIALS AND WORKMANSHIP FOR ALL PCBS" at 306.285,67.66 h1.52
  text "TO MEET OR EXCEED THE REQUIREMENTS OF:" at 306.285,65.271 h1.52
  text "X" at 297.078,62.003 h1.52
  text "ANSI IPC-A-600F CLASS ->" at 300.329,62.003 h1.52
  text "X" at 342.188,62.003 h1.52
  text "2" at 344.982,62.003 h1.52
  text "1" at 336.981,61.965 h1.52
  text "3" at 353.973,61.965 h1.52
  text "X" at 317.702,58.252 h1.52
  text "RoHS" at 320.953,58.252 h1.52
  text "OTHER" at 337.321,58.252 h1.52
  text "PER ORDER" at 347.407,58.252 h1.52
  text "ALL BOARDS MUST MEET OR EXCEED UL94-V0 REQUIREMENTS." at 288.569,54.345 h1.52
  text "PCB MUST BEAR THE UL94V-0 UL REGISTERED MATERIAL ID NUMBER" at 288.569,51.397 h1.52
  text "ADDITIONAL REQUIREMENTS:" at 287.87,47.094 h1.52
  text "MICROSECTION:" at 289.769,44.373 h1.52
  text "YES" at 312.775,44.373 h1.52
  text "REQUIRED" at 334.657,40.707 h1.52
  text "BARE BOARD ELEC. TEST:" at 289.769,40.634 h1.52
  text "NONE" at 322.935,40.634 h1.52
  text "X" at 331.66,40.634 h1.52
  text "PER ORDER" at 349.693,40.634 h1.52
  text "XX MIL VIAS REQUIRE NON-CONDUCTIVE FILL AND PLANARIZE" at 294.04,35.428 h1.5
  text "XX MIL VIAS REQUIRE CONDUCTIVE FILL AND PLANARIZE" at 294.243,32.787 h1.52
  text "OUTER XX MIL TRACES REQUIRE 50 OHM SINGLE-ENDED IMPEDANCE" at 294.218,28.637 h1.47
  text "LAYER 2 & 3 (INNER LAYERS) XX MIL WIDE, XX MIL SPACE / TRACES REQUIRE 100 OHM DIFFERENTIAL IMPEDANCE" at 294.015,22.65 h1.52
  text ".Layer_Name" at 14.656,-21.806 h1.52
M11 Gerber Information:
  lines w0.254: -7.417,-23.626 160.223,-23.626 ; -7.417,-18.462 160.274,-18.462 ; -7.417,-13.297 -7.417,-28.791 94.31,-28.791 160.274,-28.791 160.274,-13.297 -7.404,-13.297 -7.404,-28.791 32.614,-28.791 ; 55.194,-28.791 55.194,-13.297 ; 87.376,-18.462 87.376,-13.297 ; 108.712,-18.462 108.712,-13.297 ; 124.511,-28.956 124.511,-23.804
  text "ALL ARTWORK VIEWED FROM TOP SIDE" at -5.804,-16.654 h1.52
  text "BOARD #:" at 57.099,-16.654 h1.52
  text ".PRJ_Number" at 70.955,-16.654 h1.52
  text "REV:" at 92.405,-16.654 h1.52
  text ".PCB_Rev" at 99.809,-16.654 h1.52
  text "SVN REV:" at 113.69,-16.654 h1.52
  text ".VersionControl_RevNumber" at 126.543,-16.654 h1.52
  text "LAYER NAME =" at -5.804,-21.806 h1.52
  text "TID #:" at 57.099,-21.819 h1.52
  text ".TID" at 70.955,-21.819 h1.52
  text "PLOT NAME =" at -5.804,-27.034 h1.52
  text ".plot_File_Name" at 14.656,-27.034 h1.52
  text "GENERATED    :" at 57.15,-27.034 h1.52
  text ".Print_Date" at 79.235,-27.034 h1.52
  text ".Print_Time" at 97.752,-27.034 h1.52
  text "TEXAS INSTRUMENTS" at 129.87,-27.034 h1.52
M12 Stackup:
  drawing of 191 lines, arcs and shapes, not listed
  text "Layer" at 249.469,200.023 h1.52
  text "Name" at 259.88,200.023 h1.52
  text "Material" at 283.496,200.023 h1.52
  text "Thickness" at 305.334,200.023 h1.52
  text "Constant" at 321.84,200.023 h1.52
  text "Board Layer Stack" at 336.314,200.023 h1.52
  text "Top Overlay" at 259.88,196.975 h1.52
  text "Top Solder" at 259.88,193.927 h1.52
  text "Solder Resist" at 283.496,193.927 h1.52
  text "0.40mil" at 305.334,193.927 h1.52
  text "3.5" at 321.84,193.927 h1.52
  text "1" at 249.469,190.879 h1.52
  text "Top Layer" at 259.88,190.879 h1.52
  text "1.40mil" at 305.334,190.879 h1.52
  text "Dielectric1" at 259.88,187.831 h1.52
  text "FR-4 High Tg" at 283.496,187.831 h1.52
  text "59.20mil" at 305.334,187.831 h1.52
  text "4.8" at 321.84,187.831 h1.52
  text "2" at 249.469,184.783 h1.52
  text "Bottom Layer" at 259.88,184.783 h1.52
  text "1.40mil" at 305.334,184.783 h1.52
  text "Bottom Solder" at 259.88,181.735 h1.52
  text "Solder Resist" at 283.496,181.735 h1.52
  text "0.40mil" at 305.334,181.735 h1.52
  text "3.5" at 321.84,181.735 h1.52
  text "Bottom Overlay" at 259.88,178.687 h1.52
  text ".Layer_Name" at 14.656,-21.806 h1.52
M13 Component Bodies Top:
  text ".Layer_Name" at 14.656,-21.806 h1.52
M14 Component Bodies Bottom:
  text ".Layer_Name" at 14.656,-21.806 h1.52
M15 Courtyards Top:
  text ".Layer_Name" at 14.656,-21.806 h1.52
M16 Courtyards Bottom:
  text ".Layer_Name" at 14.656,-21.806 h1.52
Drill Drawing:
  circle w0.254: c136.238,83.573 r0.421
  circle w0.254: c136.238,83.573 r0.702
  lines w0.254: 135.537,62.171 136.94,62.171 136.238,60.767 135.537,62.171 ; 135.537,63.925 136.94,63.925 136.94,65.329 135.537,65.329 135.537,63.925 ; 135.537,67.083 135.537,67.434 135.888,67.785 135.537,68.135 135.537,68.486 135.888,68.486 136.238,68.135 136.589,68.486 136.94,68.486 136.94,68.135 136.589,67.785 136.94,67.434 136.94,67.083 136.589,67.083 136.238,67.434 135.888,67.083 135.537,67.083 ; 135.537,70.591 135.888,70.591 136.238,70.241 136.589,70.591 136.94,70.591 136.589,70.942 136.94,71.293 136.589,71.293 136.238,71.644 135.888,71.293 135.537,71.293 135.888,70.942 135.537,70.591 ; 135.537,73.749 135.888,73.749 135.888,73.398 136.589,73.398 136.589,73.749 136.94,73.749 136.94,74.451 136.589,74.451 136.589,74.802 135.888,74.802 135.888,74.451 135.537,74.451 135.537,73.749 ; 135.537,76.556 136.238,76.907 136.94,76.556 136.589,77.258 136.94,77.959 136.238,77.609 135.537,77.959 135.888,77.258 135.537,76.556 ; 135.537,79.714 136.94,79.714 136.94,81.117 135.537,81.117 135.537,79.714 ; 135.817,79.994 136.659,79.994 136.659,80.836 135.817,80.836 135.817,79.994
  lines w0.305: 134.264,59.82 216.344,59.82 ; 134.264,85.082 216.344,85.082 ; 142.846,56.662 142.846,88.24 ; 151.279,56.662 151.279,88.24 ; 167.448,56.662 167.448,88.24 ; 174.03,56.662 174.03,88.24 ; 183.559,56.662 183.559,88.24 ; 201.957,56.662 201.957,88.24 ; 134.264,56.662 216.344,56.662 216.344,88.24 134.264,88.24 134.264,56.662
  text "Symbol" at 136.159,86.029 h1.83
  text "Quantity" at 143.793,86.029 h1.83
  text "Finished Hole Size" at 152.226,86.029 h1.83
  text "Plated" at 168.395,86.029 h1.83
  text "Hole Type" at 174.977,86.029 h1.83
  text "Drill Layer Pair" at 184.506,86.029 h1.83
  text "Hole Tolerance" at 202.904,86.029 h1.83
  text "16" at 143.793,82.871 h1.52
  text "23.62mil (0.600mm)" at 152.226,82.871 h1.52
  text "PTH" at 168.395,82.871 h1.52
  text "Round" at 174.977,82.871 h1.52
  text "Top Layer - Bottom Layer" at 184.506,82.871 h1.52
  text "+/-1.97mil" at 202.904,82.871 h1.52
  text "16" at 143.793,79.714 h1.52
  text "23.62mil (0.600mm)" at 152.226,79.714 h1.52
  text "PTH" at 168.395,79.714 h1.52
  text "Round" at 174.977,79.714 h1.52
  text "Top Layer - Bottom Layer" at 184.506,79.714 h1.52
  text "2" at 143.793,76.556 h1.52
  text "29.53mil (0.750mm)" at 152.226,76.556 h1.52
  text "PTH" at 168.395,76.556 h1.52
  text "Round" at 174.977,76.556 h1.52
  text "Top Layer - Bottom Layer" at 184.506,76.556 h1.52
  text "8" at 143.793,73.398 h1.52
  text "33.47mil (0.850mm)" at 152.226,73.398 h1.52
  text "PTH" at 168.395,73.398 h1.52
  text "Round" at 174.977,73.398 h1.52
  text "Top Layer - Bottom Layer" at 184.506,73.398 h1.52
  text "2" at 143.793,70.241 h1.52
  text "39.37mil (1.000mm)" at 152.226,70.241 h1.52
  text "PTH" at 168.395,70.241 h1.52
  text "Round" at 174.977,70.241 h1.52
  text "Top Layer - Bottom Layer" at 184.506,70.241 h1.52
  text "3" at 143.793,67.083 h1.52
  text "55.12mil (1.400mm)" at 152.226,67.083 h1.52
  text "PTH" at 168.395,67.083 h1.52
  text "Round" at 174.977,67.083 h1.52
  text "Top Layer - Bottom Layer" at 184.506,67.083 h1.52
  text "20" at 143.793,63.925 h1.52
  text "63.00mil (1.600mm)" at 152.226,63.925 h1.52
  text "PTH" at 168.395,63.925 h1.52
  text "Round" at 174.977,63.925 h1.52
  text "Top Layer - Bottom Layer" at 184.506,63.925 h1.52
  text "4" at 143.793,60.767 h1.52
  text "70.87mil (1.800mm)" at 152.226,60.767 h1.52
  text "PTH" at 168.395,60.767 h1.52
  text "Round" at 174.977,60.767 h1.52
  text "Top Layer - Bottom Layer" at 184.506,60.767 h1.52
  text "71 Total" at 143.793,57.61 h1.52
  text ".Layer_Name" at 14.656,-21.806 h1.52
M17 Embedded Cavity:
  text ".Layer_Name" at 14.656,-21.806 h1.52
M18 Embedded Assembly:
  text ".Layer_Name" at 14.656,-21.806 h1.52
M19 Embedded Keepout:
  text ".Layer_Name" at 14.656,-21.806 h1.52

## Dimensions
0,-10.16 to 25.4,-10.16 on M2 Board Dimensions
0,0 to 0,87.63 on M2 Board Dimensions
0,0 to 125.73,0 on M2 Board Dimensions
